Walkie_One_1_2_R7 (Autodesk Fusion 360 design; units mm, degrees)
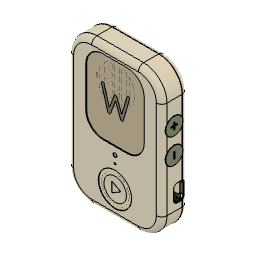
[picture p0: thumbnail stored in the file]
description: Part Number
part number: 2026-09-04-20-59-22-325
part number: 2026-09-04-20-59-24-546
part number: 2026-09-04-20-59-24-551
part number: 2026-09-04-20-59-24-554
part number: 2026-09-04-20-59-24-678
part number: Open CASCADE STEP translator 7.7 3
part number: 2026-09-04-20-59-25-589
part number: Open CASCADE STEP translator 7.7 4
part number: 2026-09-04-20-59-26-167
part number: Open CASCADE STEP translator 7.7 5
part number: 2026-09-04-20-59-26-787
